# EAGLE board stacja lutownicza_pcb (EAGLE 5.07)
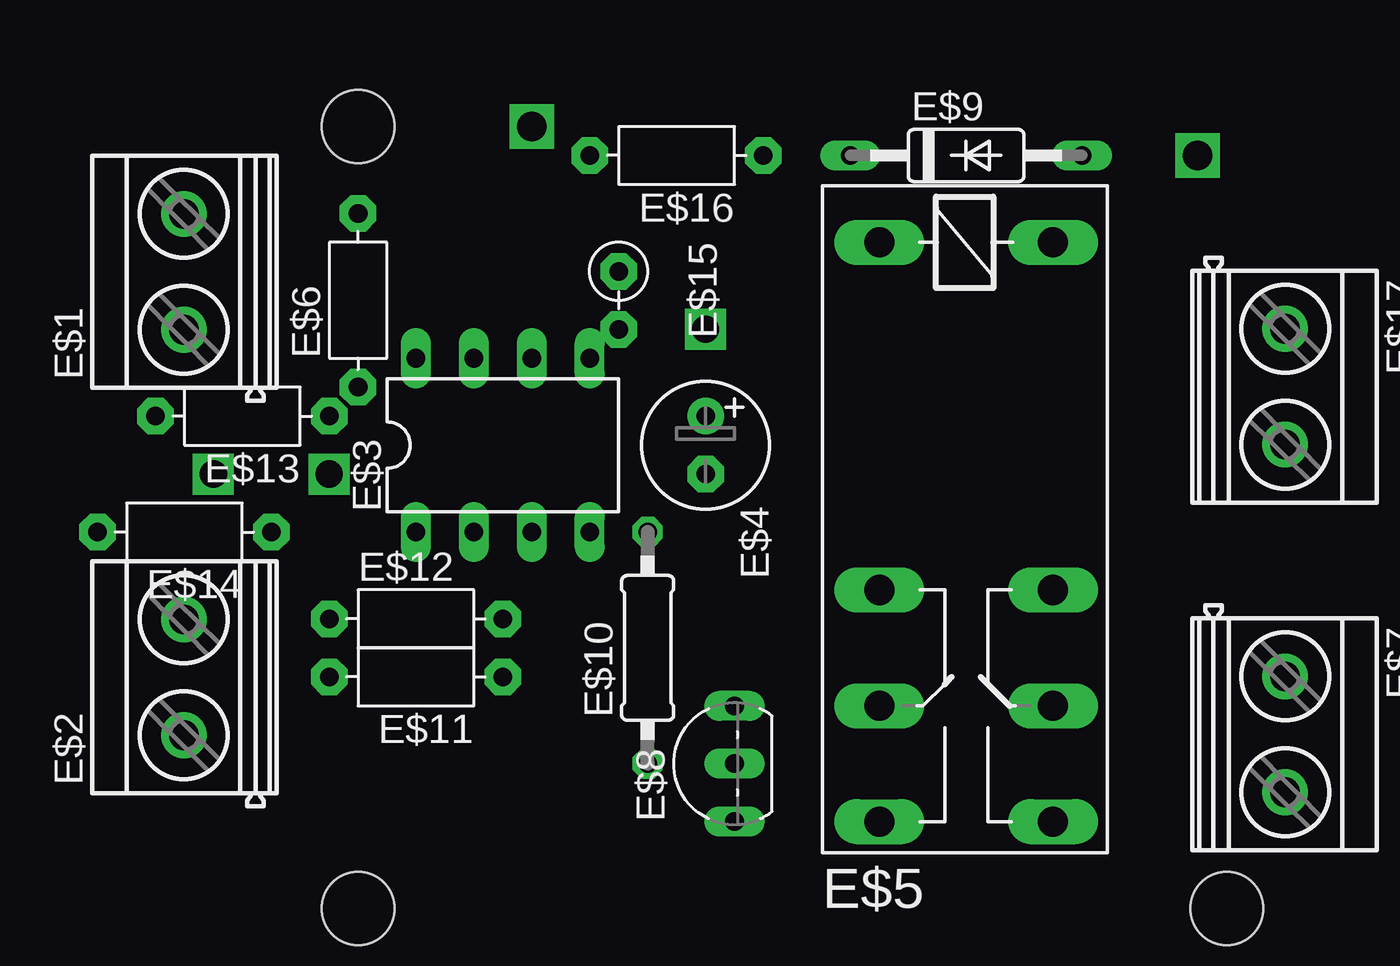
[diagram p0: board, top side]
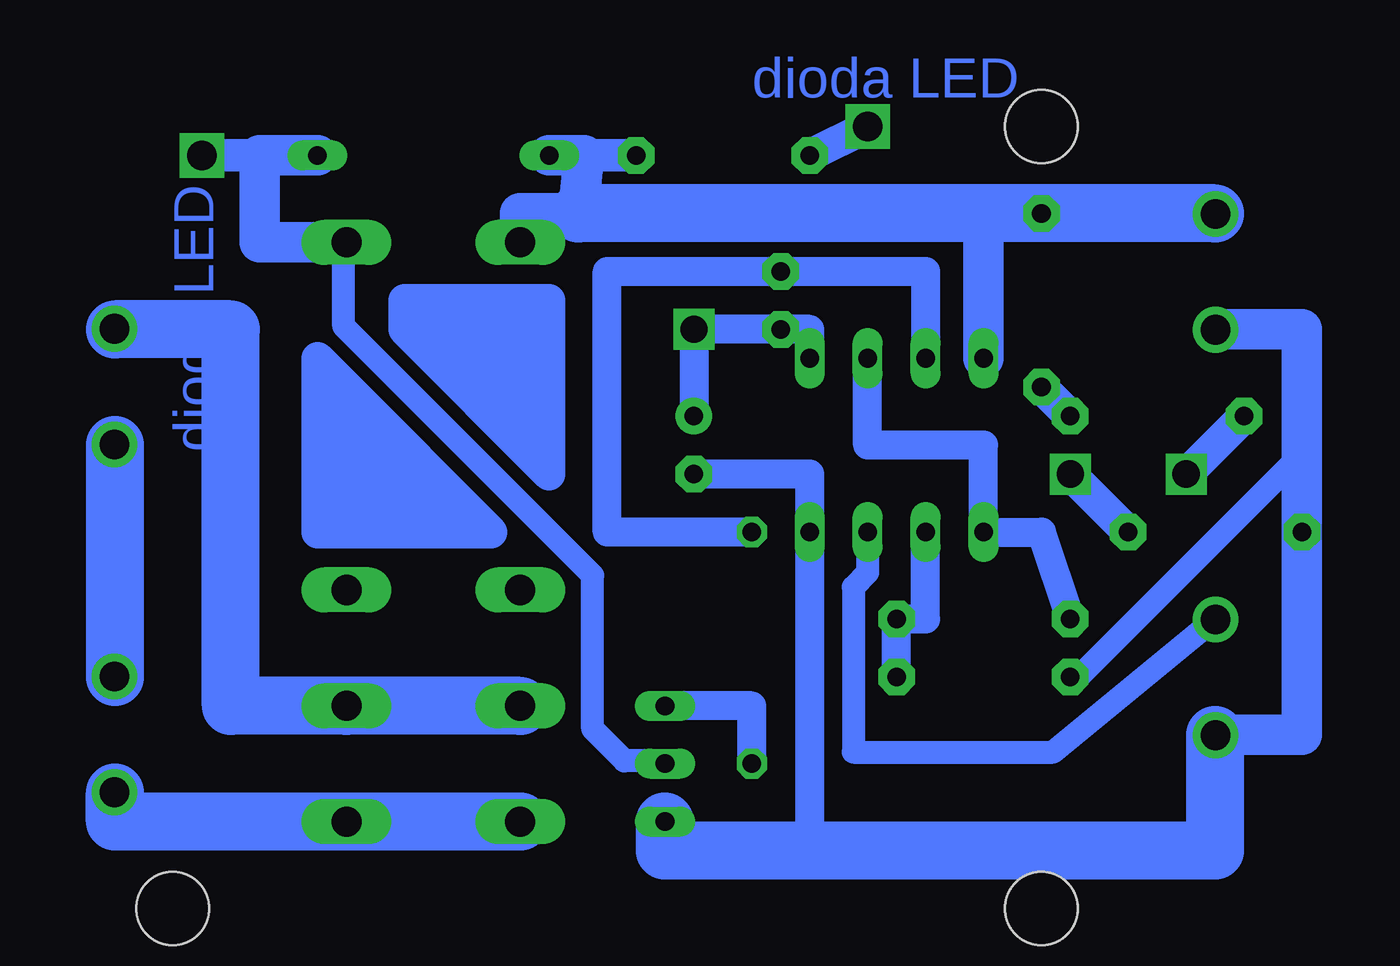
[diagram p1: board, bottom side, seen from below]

No outline drawn. Coordinates in mm, seen from the top.
Copper layers (1*16): Top 0.035mm / dielectric 1.5mm / Bottom 0.035mm
Design rules "default": minimum track width 10mil, minimum drill 24mil, track to track 8mil, track to pad 8mil, pad to pad 8mil, via to via 8mil, smd to smd 8mil, copper to edge 40mil, drill to drill 8mil, minimum pad ring 10mil, minimum via ring 8mil, stop-mask expansion 4mil, vias tented up to drill 0mil, thermal gap 10mil
Holes 3.2 mm at 53.34,0 15.24,34.29 15.24,0

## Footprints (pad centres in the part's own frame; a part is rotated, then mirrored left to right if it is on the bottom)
MKDSN1,5/2-5,08 = drill 1.3 pad 2 round: 1 -2.561,0.025; 2 2.519,0.025
DIL08 = drill 0.813 long: 1 -3.81,-3.81; 2 -1.27,-3.81; 3 1.27,-3.81; 4 3.81,-3.81; 5 3.81,3.81; 6 1.27,3.81; 7 -1.27,3.81; 8 -3.81,3.81
E2,5-6 = drill 0.813 pad 1.6 round: + -1.27,0 | drill 0.813 pad 1.6 octagon: - 1.27,0
F4052 = drill 1.321 long: 1 -3.81,3.81; 2 -3.81,-3.81; O1 11.43,-3.81; O2 11.43,3.81; P1 16.51,-3.81; P2 16.51,3.81; S1 21.59,-3.81; S2 21.59,3.81
R-7,5 = drill 0.813 pad 1.6 octagon: 1 -3.81,0; 2 3.81,0
TO92- = drill 0.813 long: 1 2.54,0; 2 0,0; 3 -2.54,0
C2992 = drill 0.813 long: A 5.08,0; C -5.08,0
0207/10 = drill 0.813 octagon: 1 -5.08,0; 2 5.08,0
RS-2,5 = drill 0.813 pad 1.6 octagon: 1 -1.27,0; 2 1.27,0

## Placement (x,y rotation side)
E$1  [MKDSN1,5/2-5,08]  7.62,27.94 90 top
E$2  [MKDSN1,5/2-5,08]  7.62,10.16 90 top
E$3  [DIL08]  21.59,20.32 0 top
E$4  [E2,5-6]  30.48,20.32 270 top
E$5  [F4052]  41.91,25.4 270 top
E$6  [R-7,5]  15.24,26.67 90 top
E$7  [MKDSN1,5/2-5,08]  55.88,7.62 270 top
E$8  [TO92-]  31.75,6.35 90 top
E$9  [C2992]  41.91,33.02 0 top
E$10  [0207/10]  27.94,11.43 90 top
E$11  [R-7,5]  17.78,10.16 180 top
E$12  [R-7,5]  17.78,12.7 0 top
E$13  [R-7,5]  10.16,21.59 180 top
E$14  [R-7,5]  7.62,16.51 180 top
E$15  [RS-2,5]  26.67,26.67 270 top
E$16  [R-7,5]  29.21,33.02 180 top
E$17  [MKDSN1,5/2-5,08]  55.88,22.86 270 top

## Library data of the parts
E$1 E$2 E$7 E$17 = con-phoenix-508
E$3 = 40xx
E$4 E$10 = rcl
E$5 = relay
E$6 E$11-E$16 = discrete
E$8 = ref-packages
E$9 = diode

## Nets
S$1: E$5.P1 E$5.P2
S$2: E$3.4 E$4.-
S$3: E$3.8
S$4: E$5.1 E$9.A
S$5: E$3.5 E$4.+
S$6: E$3.2 E$11.1 E$12.2
S$7: E$3.1 E$3.6 E$12.1
S$8: E$8.1 E$10.1
S$9: E$3.7 E$10.2
S$13: E$6.1 E$13.1
S$14: E$13.2
S$15: E$14.1
S$18: E$5.2 E$9.C E$16.1
S$19: E$16.2
S$20: E$8.3
S$21: E$5.S1 E$5.S2

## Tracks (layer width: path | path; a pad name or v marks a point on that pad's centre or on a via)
S$1
  Bottom 2.54: E$5.P1 E$5.P2 50.8,8.89 50.8,25.4 55.88,25.4
S$2
  Bottom 1.27: E$4.- 25.4,19.05 E$3.4 25.4,3.81
S$3
  Bottom 1.778: E$3.8 17.78,30.48
S$4  (via drill 1.3)
  Bottom 1.422: E$9.A v52.07,33.02
  Bottom 1.778: E$9.A 49.53,33.02 49.53,29.21 E$5.1
S$5  (via drill 1.2)
  Bottom 1.27: E$3.5 25.4,25.4 v30.48,25.4 E$4.+
S$6
  Bottom 1.27: E$3.2 20.32,12.7 E$12.2 E$11.1
S$7
  Bottom 1.27: E$3.6 22.86,20.32 17.78,20.32 E$3.1 15.24,16.51 E$12.1
S$8
  Bottom 1.27: E$10.1 27.94,8.89 E$8.1
S$9
  Bottom 1.27: E$10.2 34.29,16.51 34.29,27.94 20.32,27.94 E$3.7
S$10
  Bottom 1.016: 22.86,16.26 22.86,14.73 23.5,14.1 23.5,6.86 14.73,6.86 7.62,12.7
S$11
  Bottom 1.016: 14.1,10.16 13.59,10.16 3.68,20.07
S$12
  Bottom 1.016: 45.85,29.34 45.85,25.53 34.92,14.61 34.92,7.87 33.53,6.48 32,6.48 31.88,6.35
S$13
  Bottom 1.422: E$6.1 E$13.1
S$14  (via drill 1.2)
  Bottom 1.422: E$13.2 v8.89,19.05
S$15  (via drill 1.2)
  Bottom 1.422: v13.97,19.05 E$14.1
S$16
  Bottom 1.422: 45.72,22.86 39.37,16.51 40.64,16.51 | 45.72,22.86 46.99,24.13 46.99,16.51 40.64,16.51 | 40.64,16.51 41.91,17.78 44.45,20.32 45.72,21.59 | 45.72,21.59 45.72,17.78 43.18,17.78 44.45,19.05 | 45.72,21.59 45.72,22.86
  Bottom 1.778: 44.45,20.32 44.45,19.05 45.72,19.05 45.72,17.78 41.91,17.78
S$17
  Bottom 1.422: 36.83,22.86 36.83,20.32 | 36.83,20.32 36.83,19.05 43.18,25.4 43.18,26.67 36.83,26.67 36.83,22.86 | 36.83,22.86 38.1,21.59 41.91,25.4 | 40.64,25.4 38.1,25.4 38.1,22.86 39.37,24.13 | 40.64,24.13 36.83,20.32
  Bottom 1.778: 38.1,25.4 39.37,25.4 39.37,24.13 40.64,24.13 40.64,25.4 41.91,25.4
S$18
  Bottom 1.422: 35.56,33.02 E$16.1
  Bottom 1.778: E$9.C 35.56,33.02 35.31,33.02 35.56,30.48 38.1,30.48 E$5.2
  Bottom 2.54: 7.62,30.48 35.56,30.48
S$19  (via drill 1.3)
  Bottom 1.422: E$16.2 v22.86,34.29
S$20
  Bottom 1.778: 7.62,25.4 3.81,25.4 3.81,7.62 7.62,7.62
  Bottom 2.54: E$8.3 31.75,2.54 7.62,2.54 7.62,7.62
S$21
  Bottom 2.54: E$5.S1 44.45,3.81 E$5.S2 55.88,3.81 55.88,5.08
S$22
  Bottom 2.54: 55.88,20.32 55.88,10.16

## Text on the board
Bottom: dioda LED | dioda LED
